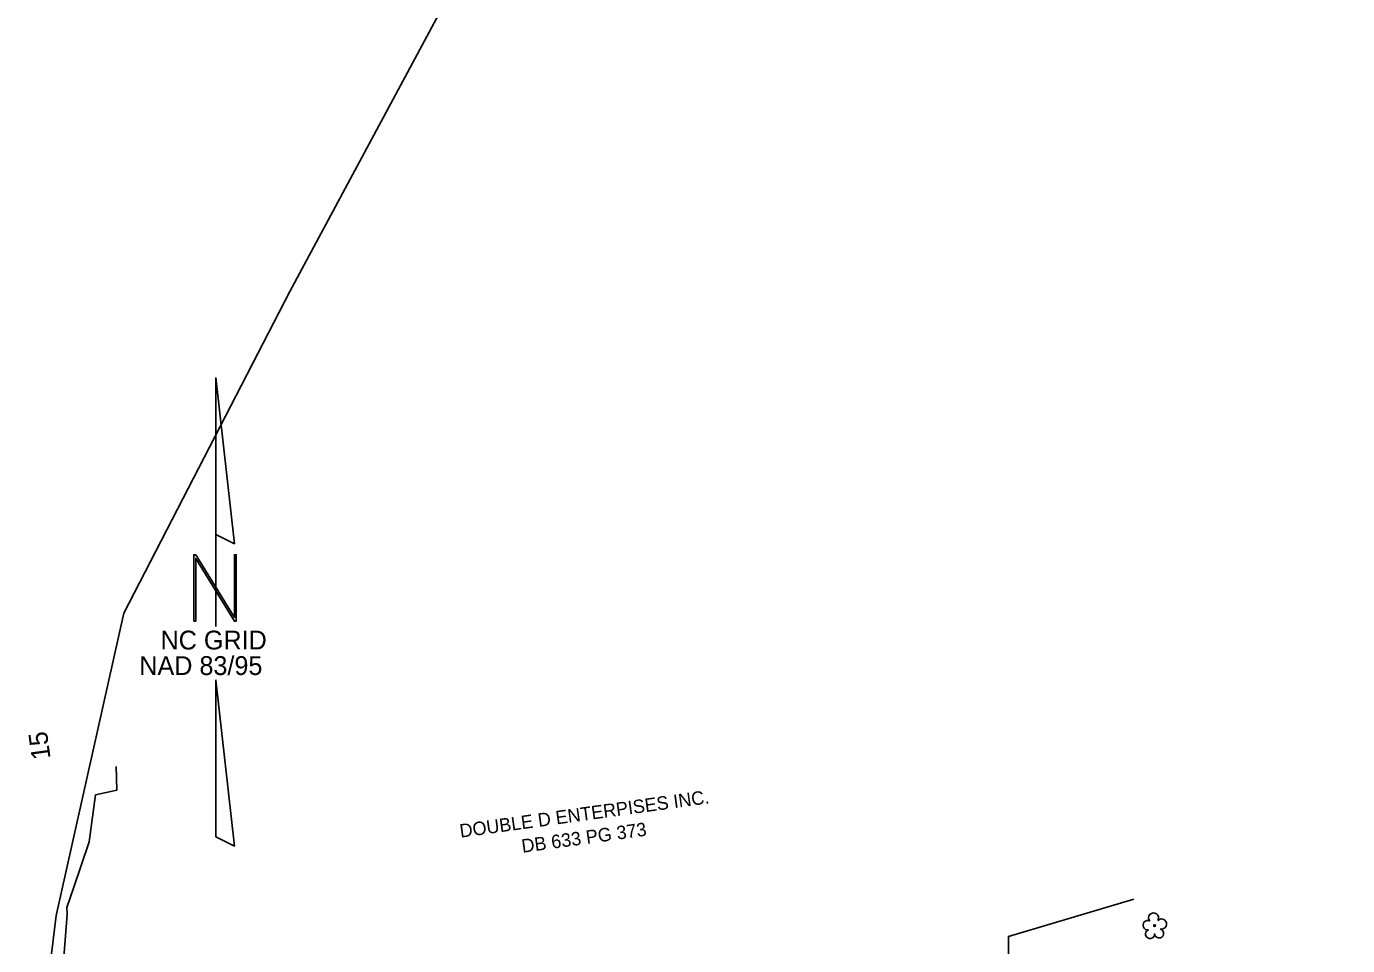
# Model space of a CAD drawing. Extents: x 2086416 to 2115205, y 575507 to 632762.
# Drawn here: x 2111574.6 to 2112066, y 581886.3 to 582228.2 of the extents above; entities that cross this region are included whole.
import ezdxf

# ---------------------------------------------------------------- set-up
doc = ezdxf.new("R2010")
doc.units = 0
for name, color, linetype in [('CTL North Arrow NAD 83 95 CELL', 7, 'Continuous'), ('DTM Contours Minor', 7, 'Continuous'), ('Exist Hydrographic Stream Bed', 7, 'Continuous'), ('Exist Property Deed Book Text', 7, 'Continuous'), ('Exist Property Owner Text', 7, 'Continuous'), ('Exist Vegetation Tree CELL', 7, 'Continuous'), ('Prop Horizontal Alignment Tick Label', 7, 'Continuous')]:
    doc.layers.add(name, color=color, linetype=linetype)

# ---------------------------------------------------------------- blocks, each defined once
blk = doc.blocks.new('EXIST VEGETATION TREE')
at = {"layer": 'Exist Vegetation Tree CELL'}
blk.add_line((0, 0), (0, 0), dxfattribs=at)
blk.add_circle((0, 0), 0.00652, dxfattribs=at)
for centre, radius, start, end in [((-0.0521, 0.0031), 0.0345, 62.66361, 279.3457), ((-0.0077, 0.0575), 0.0371, 330.16508, 219.71335), ((0.051, 0.0118), 0.038, 257.1011, 134.19993), ((-0.0341, -0.0624), 0.0338, 111.56708, 6.23104), ((0.0335, -0.058), 0.034, 181.28216, 74.55999)]:
    blk.add_arc(centre, radius, start, end, dxfattribs=at)

msp = doc.modelspace()

# ---------------------------------------------------------------- linework, layer by layer
at = {"layer": 'CTL North Arrow NAD 83 95 CELL'}
for points in [[(2111645.14, 582097.58), (2111645.14, 582039.25), (2111652.01, 582035.82)], [(2111636.91, 582007.03), (2111637.6, 582007.03), (2111637.6, 582030.35), (2111652.01, 582007.03), (2111652.7, 582007.03), (2111652.7, 582031.72), (2111652.01, 582031.72), (2111652.01, 582008.39), (2111637.6, 582031.72), (2111636.91, 582031.72)], [(2111645.14, 581926.74), (2111652.01, 581923.33), (2111645.14, 581985.07)]]:
    msp.add_lwpolyline(points, close=True, dxfattribs=at)
msp.add_lwpolyline([(2111645.14, 582039.25), (2111645.14, 582004.95)], dxfattribs=at)
at = {"layer": 'DTM Contours Minor'}
for points in [[(2111608, 581952.88), (2111608.27, 581944.13), (2111600.33, 581942.36), (2111598.01, 581924.92), (2111592.16, 581907.71), (2111589.71, 581900.42), (2111589.76, 581898.02), (2111588.05, 581875.59), (2111589.38, 581872.68), (2111592.31, 581865.53), (2111601.58, 581850.31), (2111599.5, 581843.31), (2111603.29, 581825.19), (2111603.3, 581811.34), (2111603.07, 581800.25), (2111592.15, 581795.07), (2111575.25, 581779.23)], [(2111986.57, 581903.53), (2111939.89, 581889.69), (2111940.22, 581859.65), (2111950.16, 581856.54), (2111948.11, 581845.47), (2111951.21, 581831.21), (2111961.67, 581808.41), (2111961.19, 581805.94), (2111962.39, 581807.77), (2111962.43, 581807.8), (2111962.19, 581798.43), (2111965.32, 581789.35), (2111965.47, 581786.59), (2111973.88, 581778.03), (2111977.11, 581774.63), (2111980.39, 581770.88), (2111987.46, 581769.35), (2111990.76, 581766.29)]]:
    msp.add_lwpolyline(points, dxfattribs=at)
at = {"layer": 'Exist Hydrographic Stream Bed'}
msp.add_lwpolyline([(2112129.65, 582477.71), (2111835.9, 582368.96), (2111727.15, 582231.15), (2111672.65, 582129.59), (2111610.9, 582009.96), (2111585.65, 581897.53), (2111574.65, 581806.9), (2111574.65, 581727.08), (2111582.9, 581679.52), (2111589.15, 581643.7), (2111621.9, 581589.33), (2111665.4, 581516.77), (2111701.65, 581379.01), (2111737.9, 581248.45), (2111785.15, 581103.39)], dxfattribs=at)

# ---------------------------------------------------------------- block references
at = {"layer": 'Exist Vegetation Tree CELL', "xscale": 50, "yscale": 50}
msp.add_blockref('EXIST VEGETATION TREE', (2111994.25, 581893.73), dxfattribs=at)

# ---------------------------------------------------------------- texts
at = {"layer": 'CTL North Arrow NAD 83 95 CELL'}
for s, p in [('NC GRID', (2111624.52, 581996.46)), ('NAD 83/95', (2111616.63, 581986.96))]:
    msp.add_text(s, height=7, dxfattribs=at).set_placement(p)
at = {"layer": 'Exist Property Deed Book Text'}
msp.add_text('DB 633 PG 373', height=5, rotation=7.8831, dxfattribs=at).set_placement((2111759.15, 581920.8))
at = {"layer": 'Exist Property Owner Text'}
msp.add_text('DOUBLE D ENTERPISES INC.', height=5, rotation=7.8831, dxfattribs=at).set_placement((2111736.13, 581926.42))
at = {"layer": 'Prop Horizontal Alignment Tick Label'}
msp.add_text('15', height=7, rotation=97.771, dxfattribs=at).set_placement((2111583.65, 581955.97))

doc.saveas('drawing.dxf')
